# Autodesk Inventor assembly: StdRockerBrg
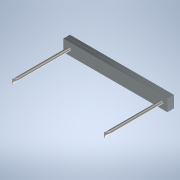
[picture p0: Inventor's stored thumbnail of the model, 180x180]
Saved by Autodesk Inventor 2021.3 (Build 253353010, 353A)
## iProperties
RuleStatus: InUse
Created: 2019-05
Part Number: StdRockerBrg
Document SubType Name: Assembly
Designer: u1426
AnchorBoltEmbed: 15.000 in
MasonryPLThickness: 1.500 in
SolePLThickness: 1.250 in
BearingLength: 44.000 in
NoSwedges: 4.000 in
ExpansionCapLength: 24.000 in
AnchorDiameter: 1.250 in
AnchorEdgeDist: 2.500 in
BearingWidth: 5.000 in
Author: u1426
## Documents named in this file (5)
- S:\Bridge_CADD\Other\SampleBridgeInventor\StdRockerBrgAB.iam
- S:\Bridge_CADD\Other\SampleBridgeInventor\StdRockerBrgMasonry.ipt
- S:\Bridge_CADD\Other\SampleBridgeInventor\StdRockerBrgSole.ipt
- S:\Bridge_CADD\Other\SampleBridgeInventor\AnchorBolt.ipt
- S:\Bridge_CADD\Other\SampleBridgeInventor\ExpansionCap.ipt
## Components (4 placed, 3 different names)
1. StdRockerBrgMasonry:1 — Flush:5, Flush:6, Flush:7, Flush:8, Flush:9, Flush:10, Flush:29, Flush:12, Mate to UCSXY, Mate to USCXZ, Mate to USCYZ
2. StdRockerBrgSole:1 — Mate:1, Flush:11, Flush:29
3. ExpansionCap:1 — Flush:5, Flush:7, Flush:9
4. ExpansionCap:2 — Flush:6, Flush:8, Flush:10
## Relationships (13: Flush 9, Mate 4)
- Mate:1: StdRockerBrgSole:1
- Flush:5: StdRockerBrgMasonry:1 ↔ ExpansionCap:1
- Flush:6: StdRockerBrgMasonry:1 ↔ ExpansionCap:2
- Flush:7: StdRockerBrgMasonry:1 ↔ ExpansionCap:1
- Flush:8: StdRockerBrgMasonry:1 ↔ ExpansionCap:2
- Flush:9: StdRockerBrgMasonry:1 ↔ ExpansionCap:1
- Flush:10: StdRockerBrgMasonry:1 ↔ ExpansionCap:2
- Flush:11: StdRockerBrgSole:1
- Flush:29: StdRockerBrgMasonry:1 ↔ StdRockerBrgSole:1
- Flush:12: StdRockerBrgMasonry:1
- Mate to UCSXY: StdRockerBrgMasonry:1
- Mate to USCXZ: StdRockerBrgMasonry:1
- Mate to USCYZ: StdRockerBrgMasonry:1
## Named parameters: EmbedConcrete = 381 mm, Protrusion = 177.8 mm
